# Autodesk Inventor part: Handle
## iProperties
Created: 2009-03
Part Number: Handle
Document SubType Name: Modeling
Designer: tangg
Density: 7.85 g/cm^3
Material: Steel
Mass: 68.364 g
Surface Area: 180.393 cm^2
Volume: 8.70879 cm^3
Author: tangg
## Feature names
1. Extrusion2
2. Fillet1
3. Shell2
4. Extrusion3
5. Extrusion4
